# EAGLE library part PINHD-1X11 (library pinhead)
PIN HEADER
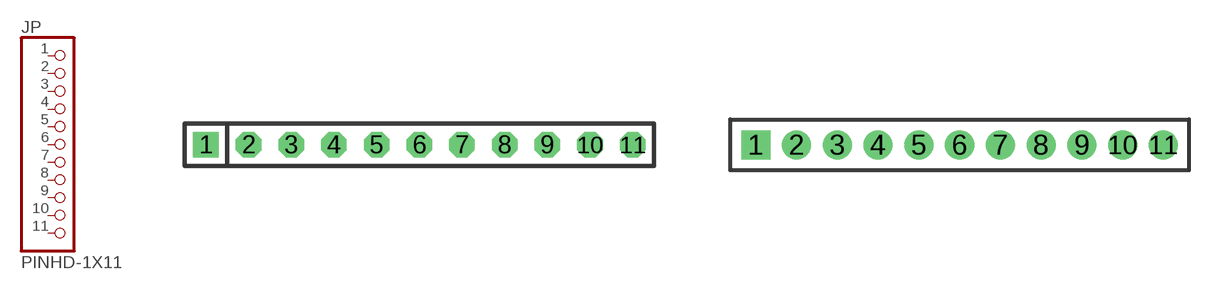
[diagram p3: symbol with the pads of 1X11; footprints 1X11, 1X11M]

Designator prefix JP

## PINHD-1X11  [1X11]
1  1  pas
2  2  pas
3  3  pas
4  4  pas
5  5  pas
6  6  pas
7  7  pas
8  8  pas
9  9  pas
10  10  pas
11  11  pas

## PINHD-1X11M  [1X11M]
Pads as for 1X11

## Footprint 1X11 (pad centres in mm)
PIN HEADER - 0.1"
drill 1.016 square: 1 -12.7,0
drill 1.016 octagon: 2 -10.16,0; 3 -7.62,0; 4 -5.08,0; 5 -2.54,0; 6 0,0; 7 2.54,0; 8 5.08,0; 9 7.62,0; 10 10.16,0; 11 12.7,0

## Footprint 1X11M (pad centres in mm)
PIN HEADER - 2MM"
drill 0.914 square: 1 -10,0
drill 0.914 round: 2 -8,0; 3 -6,0; 4 -4,0; 5 -2,0; 6 0,0; 7 2,0; 8 4,0; 9 6,0; 10 8,0; 11 10,0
